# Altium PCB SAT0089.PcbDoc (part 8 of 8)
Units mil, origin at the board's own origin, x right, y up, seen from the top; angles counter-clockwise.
Board outline 4075 x 2715 mil, 6 copper layers (Top Layer, InternalPlane1, MidLayer1, Internal Plane 3, InternalPlane2, Bottom Layer), stack 67.4 mil thick; 538 components, 405 nets, 1716 pads, 1236 vias.
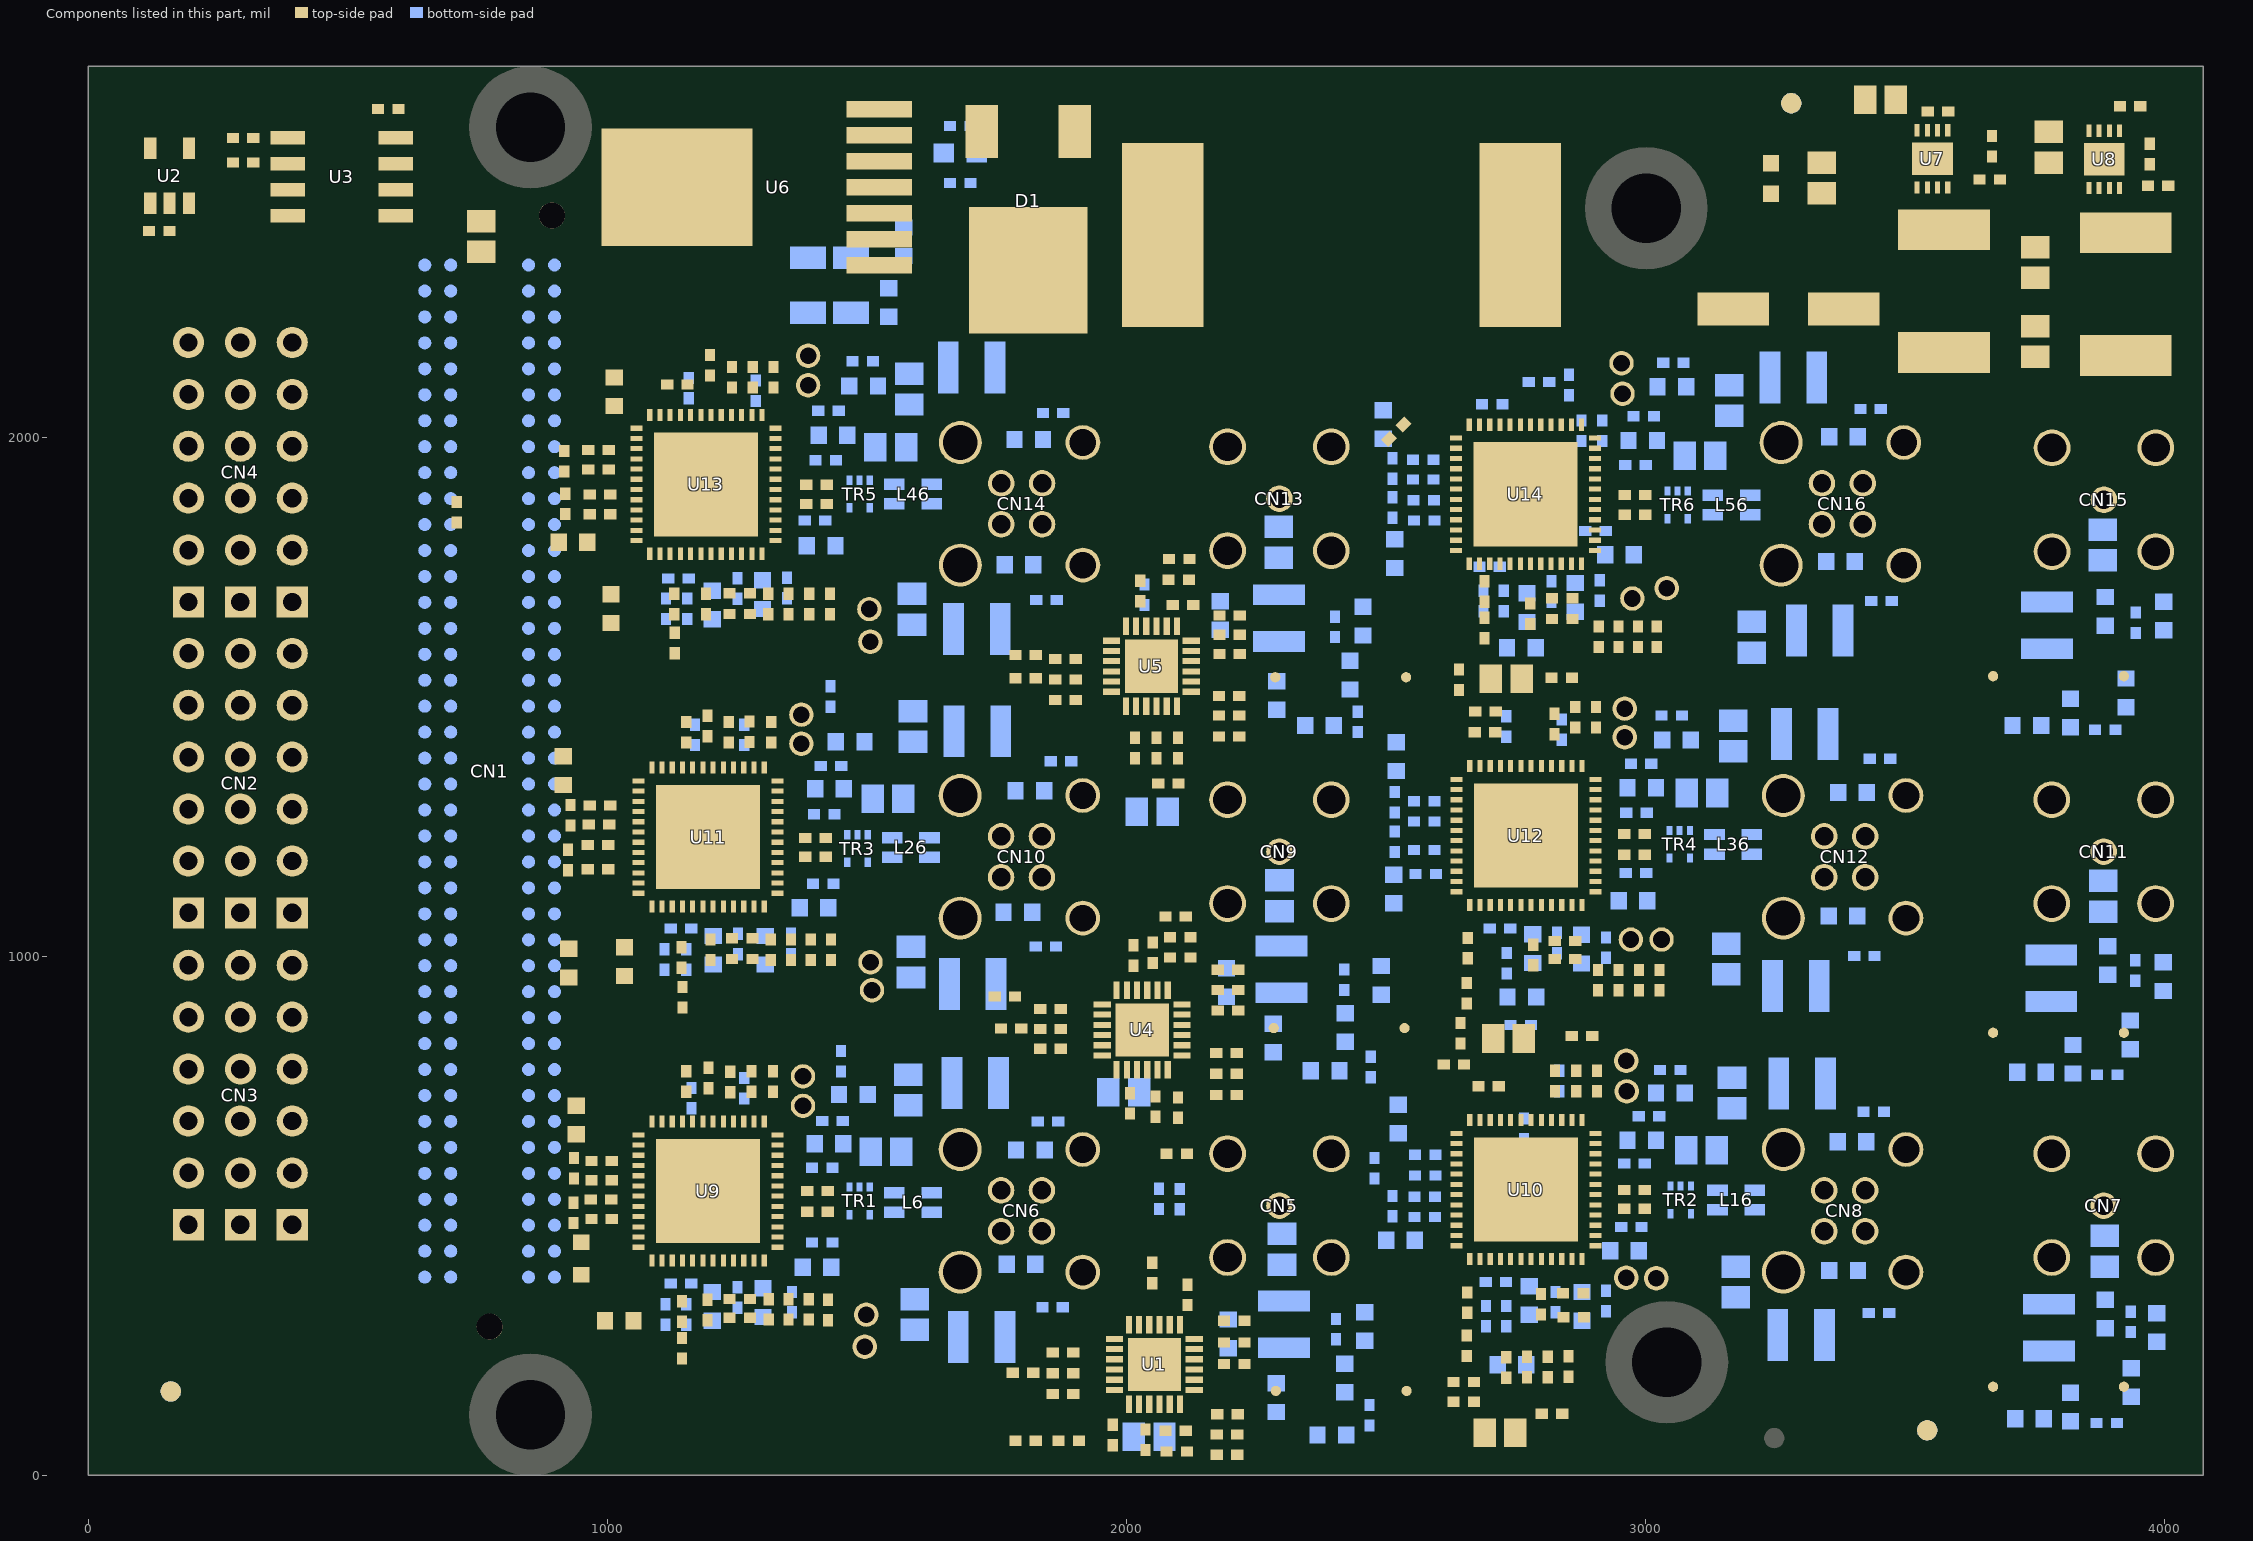
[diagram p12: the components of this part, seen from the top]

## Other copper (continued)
Internal Plane 3 (plane layer: these items are gaps in the copper):
  lines w12: 1015,855 1015,955 ; 1015,855 1060,810 ; 1015,855 1060,810 ; 1015,855 1015,955 ; 1015,955 1070,1010 ; 1015,955 1020,960 1070,1010 ; 1060,810 1060,600 900,600 900,890 900,1020 970,1020 970,1120 915,1120 915,1265 833,1265 833,2100 1005,2100 1010,2100 1010,1845 915,1845 915,1775 1010,1775 1010,1380 1065,1380 1070,1380 1070,1010 ; 1060,810 1060,570 1060,320 1025,320 1025,240 1160,240 1160,455 1160,680 1160,805 1090,875 1090,935 1165,935 1165,1140 1165,1510 1090,1510 1085,1510 1085,1675 1010,1675 1010,1385 1070,1385 1070,1010 ; 1390,1590 1400,1600 ; 1390,1590 1390,1310 1400,1295 1400,745 ; 1390,1590 1390,1305 1400,1290 1400,745 ; 1390,1590 1400,1600 ; 1390,1670 1230,1670 1230,1470 1230,1460 1305,1385 1305,240 1305,125 2045,125 2045,620 2020,620 2020,685 2440,685 2440,605 2515,605 2515,745 2080,745 2080,785 2190,785 2190,1045 2100,1135 2100,1340 2155,1395 2155,1575 1825,1575 1725,1575 1725,1545 1725,1485 1725,1475 1725,1445 1995,1445 2040,1400 2040,1395 2040,1345 2040,1135 2040,1015 2060,1015 2095,1015 2095,950 1820,950 1820,900 1710,900 1710,820 1710,760 1960,760 1960,270 1430,270 1430,715 ; 1390,1670 1400,1670 ; 1390,1670 1400,1670 ; 1390,1670 1390,2165 1495,2165 1495,1750 1535,1750 1565,1720 1565,1525 1480,1525 1480,1245 1480,1070 1570,1070 1590,1050 1590,745 1560,715 1490,715 1430,715 ; 1400,745 1430,715 ; 1400,745 1430,715 ; 1400,1600 1400,1670 ; 1400,1600 1400,1670 ; 2985,2160 3610,2160 ; 2985,2160 2985,820 2980,820 2840,820 2840,1175 2855,1175 2855,1235 2855,1375 2835,1375 2835,1665 2800,1665 2800,1975 2800,1991 2655,1991 2655,1940 2495,1940 2495,1965 2495,2030 2496,2041 2594,2041 2615,2062 2615,2170 2615,2265 3475,2265 3475,2315 3610,2315 3610,2160 ; 2985,2160 2985,750 2745,750 2745,1610 2665,1610 2665,900 2665,225 2675,225 2750,225 2750,235 2750,495 2820,565 2900,645 3115,645 3115,1330 3115,2020 3115,2035 3675,2035 3675,2190 3760,2190 3760,2135 3930,2135 3930,2155 3930,2190 3930,2305 3610,2305 3610,2160 ; 2985,2160 3610,2160
  lines w20: 4010,-1.1 58.7,-1.1 cw(c58.7,57.95) -0.35,57.95 -0.35,2656.38 cw(c58.7,2656.38) 58.7,2715.43 4015,2715.4 ; 4017.05,-1.1 ccw(c4017.05,57.95) 4076.1,57.95 ; 4017.05,2715.43 cw(c4017.05,2656.38) 4076.1,2656.38 ; 4076.1,47.95 4076.1,2646.38
  text ".Layer_Name" at 572,-861.49 h60

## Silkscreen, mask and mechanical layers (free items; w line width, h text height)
Top Overlay:
  circle w5.91: c503.32,60.58 r23.42
  region: 3026,880 3026,866 3052,873
  region: 2876,169 2894,136 2909,153
  region: 460,1705 460,1655 505,1655 505,1705
  region: 465,1110 465,1060 510,1060 510,1110
  region: 455,505 455,455 500,455 500,505
  lines w4: 2884,162 2941,105 2941,103 ; 2963,909 2999,873 3043,873
  text "C" at 497,51 h18.75
  text "2014" at 545,43 h31.25
  text ".Layer_Name" at 577,-858.49 h60
Bottom Overlay:
  rectangle: 1833,2174.5 2133,2274.5
  text ".PCB_Rev" at 2335,2184 h60
  text ".PRJ_Number" at 2799,2184.5 h60
  text "-" at 2198,2174 h60
  text ".Layer_Name" at 577,-858.49 h60
Top Paste:
  region: 2689.91,1812.04 2756.83,1812.04 2756.83,1878.97 2689.91,1878.97
  region: 2690.91,563.59 2757.83,563.59 2757.83,630.52 2690.91,630.52
  region: 2689.91,1902.59 2756.83,1902.59 2756.83,1969.52 2689.91,1969.52
  region: 2690.91,1245.59 2757.83,1245.59 2757.83,1312.52 2690.91,1312.52
  region: 2690.91,1155.04 2757.83,1155.04 2757.83,1221.97 2690.91,1221.97
  region: 2690.91,473.04 2757.83,473.04 2757.83,539.97 2690.91,539.97
  region: 1201.46,1921.59 1268.39,1921.59 1268.39,1988.52 1201.46,1988.52
  region: 1201.46,1831.04 1268.39,1831.04 1268.39,1897.97 1201.46,1897.97
  region: 1205.46,1241.59 1272.39,1241.59 1272.39,1308.52 1205.46,1308.52
  region: 1205.46,1151.04 1272.39,1151.04 1272.39,1217.97 1205.46,1217.97
  region: 1205.46,560.59 1272.39,560.59 1272.39,627.52 1205.46,627.52
  region: 1205.46,470.04 1272.39,470.04 1272.39,536.97 1205.46,536.97
  region: 2780.46,1812.04 2847.39,1812.04 2847.39,1878.97 2780.46,1878.97
  region: 2781.46,563.59 2848.39,563.59 2848.39,630.52 2781.46,630.52
  region: 2780.46,1902.59 2847.39,1902.59 2847.39,1969.52 2780.46,1969.52
  region: 2781.46,1245.59 2848.39,1245.59 2848.39,1312.52 2781.46,1312.52
  region: 2781.46,1155.04 2848.39,1155.04 2848.39,1221.97 2781.46,1221.97
  region: 2781.46,473.04 2848.39,473.04 2848.39,539.97 2781.46,539.97
  region: 1110.91,1921.59 1177.83,1921.59 1177.83,1988.52 1110.91,1988.52
  region: 1110.91,1831.04 1177.83,1831.04 1177.83,1897.97 1110.91,1897.97
  region: 1114.91,1241.59 1181.83,1241.59 1181.83,1308.52 1114.91,1308.52
  region: 1114.91,1151.04 1181.83,1151.04 1181.83,1217.97 1114.91,1217.97
  region: 1114.91,560.59 1181.83,560.59 1181.83,627.52 1114.91,627.52
  region: 1114.91,470.04 1181.83,470.04 1181.83,536.97 1114.91,536.97
  region: 3248.31,92.08 3240.63,90.55 3234.11,86.2 3229.76,79.69 3228.24,72.01 3229.76,64.33 3234.11,57.82 3240.63,53.46 3248.31,51.94 3255.99,53.46 3262.5,57.82 3266.85,64.33 3268.38,72.01 3266.85,79.69 3262.5,86.2 3255.99,90.55 3248.31,92.08
  text ".Layer_Name" at 577,-858.49 h60
Bottom Paste:
  text ".Layer_Name" at 577,-858.49 h60
Top Solder:
  region: 3248.31,131.35 3236.73,130.21 3225.6,126.83 3215.34,121.35 3206.35,113.97 3198.97,104.98 3193.48,94.72 3190.11,83.58 3188.97,72.01 3190.11,60.43 3193.48,49.3 3198.97,39.04 3206.35,30.05 3215.34,22.67 3225.6,17.18 3236.73,13.81 3248.31,12.67 3259.88,13.81 3271.02,17.18 3281.28,22.67 3290.27,30.05 3297.65,39.04 3303.13,49.3 3306.51,60.43 3307.65,72.01 3306.51,83.58 3303.13,94.72 3297.65,104.98 3290.27,113.97 3281.28,121.35 3271.02,126.83 3259.88,130.21 3248.31,131.35
  text ".Layer_Name" at 577,-858.49 h60
  text ".Layer_Name" at 577,-858.49 h60
Bottom Solder:
  text ".Layer_Name" at 577,-858.49 h60
Drill Guide:
  text ".Layer_Name" at 577,-858.49 h60
M1 Board Outline:
  the board outline again, w10
  text ".Layer_Name" at 577,-858.49 h60
M2 Board Dimensions:
  rectangle: -0.5,-285.5 124.5,-160.5
  rectangle: 124.5,-410.5 499.5,-285.5
  lines w7: -0.5,-285.5 999.5,-285.5 ; 124.5,-410.5 124.5,-160.5 ; 249.5,-410.5 249.5,-160.5 ; 499.5,-410.5 499.5,-160.5 ; 749.5,-410.5 749.5,-160.5 ; -0.5,-410.5 999.5,-410.5 999.5,-160.5 -0.5,-160.5 -0.5,-410.5
  lines w10: -0.5,-475.5 -0.5,-455.5 ; 59.5,-485.5 -0.5,-465.5 ; 59.5,-445.5 -0.5,-465.5 ; 223.58,-465.5 -0.5,-465.5 ; 775.42,-465.5 999.5,-465.5 ; 939.5,-485.5 999.5,-465.5 ; 939.5,-445.5 999.5,-465.5 ; 999.5,-475.5 999.5,-455.5
  text "1000 (mil)" at 233.58,-501.49 h60
  text ".Layer_Name" at 577,-858.49 h60
M3 3D STEP Top:
  text ".Layer_Name" at 577,-858.49 h60
M4 3D STEP Bottom:
  text ".Layer_Name" at 577,-858.49 h60
M5 Assembly Top:
  lines w10: -292,-930.17 6308,-930.17 ; -292,-726.83 6310,-726.83 ; -292,-523.5 -292,-1133.5 3713,-1133.5 6310,-1133.5 6310,-523.5 -291.5,-523.5 -291.5,-1133.5 1284,-1133.5 ; 2173,-1133.5 2173,-523.5 ; 3440,-726.83 3440,-523.5 ; 4280,-726.83 4280,-523.5 ; 4902,-1140 4902,-937.17
  text "COMPONENTS MARKED 'DNP' SHOULD NOT BE POPULATED." at 1153.5,-318.5 h60
  text "ASSEMBLY VARIANT:" at 1153,-434 h60
  text ".VariantName" at 2189,-434 h60
  text "PCB VIEWED FROM TOP SIDE" at -228.5,-655.67 h60
  text "BOARD #:" at 2248,-655.67 h60
  text ".PRJ_Number" at 2793.5,-655.67 h60
  text "REV:" at 3638,-655.67 h60
  text ".PCB_Rev" at 3929.5,-655.67 h60
  text "SVN REV:" at 4476,-655.67 h60
  text ".VersionControl_RevNumber" at 4982,-655.67 h60
  text "IGNORE ->" at -228.5,-858.49 h60
  text "PLOT NAME =" at -228.5,-1064.34 h60
  text ".plot_File_Name" at 577,-1064.34 h60
  text "GENERATED    :" at 2250,-1064.34 h60
  text ".Print_Date" at 3119.5,-1064.34 h60
  text ".Print_Time" at 3848.5,-1064.34 h60
  text "TEXAS INSTRUMENTS" at 5113,-1064.34 h60
M6 Assembly Bottom:
  lines w10: -292.5,-727.33 6309.5,-727.33 ; -290.5,-930.67 6309.5,-930.67 ; 1115.5,-1140.5 1115.5,-937.67 ; 1737.5,-727.33 1737.5,-524 ; 2577.5,-727.33 2577.5,-524 ; 3844.5,-1134 3844.5,-524 ; 4733.5,-1134 6309,-1134 6309,-524 -292.5,-524 -292.5,-1134 2304.5,-1134 6309.5,-1134 6309.5,-524
  text "COMPONENTS MARKED 'DNP' SHOULD NOT BE POPULATED." at 6102,-318 h60
  text ".VariantName" at 5058,-434 h60
  text "ASSEMBLY VARIANT:" at 6097,-434 h60
  text ".VersionControl_RevNumber" at 1035.5,-656.17 h60
  text "SVN REV:" at 1541.5,-656.17 h60
  text ".PCB_Rev" at 2088,-656.17 h60
  text "REV:" at 2379.5,-656.17 h60
  text ".PRJ_Number" at 3224,-656.17 h60
  text "BOARD #:" at 3769.5,-656.17 h60
  text "PCB VIEWED FROM BOTTOM SIDE" at 6246,-656.17 h60
  text "IGNORE ->" at 2547.85,-858.49 h60
  text "TEXAS INSTRUMENTS" at 904.5,-1064.84 h60
  text ".Print_Time" at 2169,-1064.84 h60
  text ".Print_Date" at 2898,-1064.84 h60
  text "GENERATED    :" at 3767.5,-1064.84 h60
  text ".plot_File_Name" at 5440.5,-1064.84 h60
  text "PLOT NAME =" at 6246,-1064.84 h60
M9 Title Sheet:
  drawing of 57 lines, arcs and shapes, not listed
  text "1" at 739.84,8036.5 h70
  text "2" at 3235.5,8036.5 h70
  text "3" at 5724.84,8036.5 h70
  text "4" at 8231.51,8036.5 h70
  text "5" at 10730.5,8036.5 h70
  text "6" at 13235.5,8036.5 h70
  text "A" at -416.5,6893.5 h70
  text "A" at 14383.5,6893.5 h70
  text "B" at -416.5,4513.5 h70
  text "B" at 14383.5,4513.5 h70
  text "C" at -416.5,2138.5 h70
  text "C" at 14383.5,2138.5 h70
  text "PROJECT TITLE:" at 11343.5,277.5 h45
  text ".PRJ_Title" at 11393.5,144.17 h70
  text "DESIGNED FOR:" at 11343.5,-23.5 h45
  text ".PRJ_Customer" at 11393.5,-163.5 h70
  text "D" at -416.5,-231.5 h70
  text "D" at 14383.5,-231.5 h70
  text "FILE NAME:" at 11343.5,-323.5 h45
  text ".PCB_File_Name_No_Path" at 11393.5,-443.5 h70
  text "Texas Instruments (TI) and/or its licensors do not warrant the accuracy or completeness of this specification" at 6374,-605.34 h45
  text "ENGINEER:" at 11343.5,-613.5 h45
  text "LAYOUT BY:" at 12848.5,-613.5 h45
  text "or any information contained therein. TI and/or its licensors do not warrant that this design will meet" at 6329.01,-718 h45
  text ".PRJ_Engineer" at 11393.5,-768.49 h70
  text ".PCB_Layout" at 12899,-768.49 h70
  text "the specifications, will be suitable for your application or fit for any particular purpose, or will operate in" at 6329.01,-830.67 h45
  text ".Layer_Name" at 577,-858.49 h60
  text "ALTIUM DESIGNER VERSION:" at 12848.5,-923.5 h45
  text "an implementation. TI and/or its licensors do not warrant that the design is production worthy. You should" at 6329.01,-943.33 h45
  text "completely validate and test your design implementation to confirm the system functionality for your application." at 6374,-1056 h45
  text ".print_Scale" at 11393.5,-1056.83 h70
  text ".Application_BuildNumber" at 12899,-1056.83 h70
  text "1" at 739.84,-1263.5 h70
  text "2" at 3235.5,-1263.5 h70
  text "3" at 5724.84,-1263.5 h70
  text "4" at 8231.51,-1263.5 h70
  text "5" at 10730.5,-1263.5 h70
  text "6" at 13235.5,-1263.5 h70
M10 Fab Notes:
  drawing of 212 lines, arcs and shapes, not listed
  text "DESIGN INFORMATION" at 12381.02,6810 h60
  text "(REFER ALSO ARRAY/PANEL PROFILING INFORMATION)" at 12019.46,6648.29 h60
  text "BOARD SIZE" at 11333.46,6644 h60
  text "2715MIL" at 11795.78,6516.18 h60
  text "X" at 12301.46,6516.18 h60
  text "4075MIL" at 12532.78,6516.18 h60
  text "Number of Layers :" at 11736.46,6319 h60
  text "6" at 12831.27,6309 h60
  text "MIN. TRACK WIDTH:" at 11736.46,6180 h60
  text "4" at 12832.7,6180 h60
  text "MIL" at 12987.46,6180 h60
  text "MIN. CLEARANCE:" at 11736.46,6048 h60
  text "5" at 12832.7,6048 h60
  text "MIL" at 12987.46,6048 h60
  text "MIN. VIA PAD SIZE:" at 11736.46,5916 h60
  text "19" at 12802.71,5916 h60
  text "MIL" at 12987.46,5916 h60
  text "0.05mm (2MIL)" at 12431.46,5774.29 h60
  text "MINIMUM ANNULAR RING" at 11407.23,5770 h60
  text "EXTERNAL" at 13139.46,5770 h60
  text "PER" at 11607.23,5652 h60
  text "IPC-D-275 CLASS 2 LEVEL C" at 11827.23,5652 h60
  text "MIL, HOLES" at 13315.46,5539.71 h60
  text "+/-" at 12923,5539 h60
  text "+/-" at 13777,5539 h60
  text "REGISTRATION TOLERANCES:" at 11407.23,5534 h60
  text "METAL" at 12607,5534 h60
  text "5" at 13183.2,5534 h60
  text "3" at 14016.2,5534 h60
  text "MIL" at 14132.46,5534 h60
  text "MATERIAL:" at 11332.46,5324.54 h60
  text "FR-4 High Tg" at 12318.9,5184.21 h60
  text "FR-408" at 11753.46,5175.64 h60
  text "X" at 12165.46,5175.64 h60
  text "OTHER" at 13241.46,5175.64 h60
  text "62 MIL (1.6mm) +/-10%" at 12073.56,5012.92 h60
  text "THICKNESS:" at 11407.23,5008.64 h60
  text "X" at 11945.4,5008.64 h60
  text "OTHER" at 13358.46,5008.64 h60
  text "TOLERANCE:" at 11407.23,4850.64 h60
  text "X" at 12246.53,4850.64 h60
  text "ANSI IPC-6012 TYPE 3 CLASS 2" at 12433.48,4850.64 h60
  text "OTHER +/-" at 12433.46,4694.64 h60
  text "BOW & TWIST:" at 11407.23,4537.64 h60
  text "X" at 12246.53,4537.64 h60
  text "ANSI IPC-6012 TYPE 3 CLASS 2" at 12433.48,4537.64 h60
  text "OTHER +/-" at 12433.46,4379.13 h60
  text "COPPER THICKNESS (FINISHED):" at 11332.46,4243.64 h60
  text "1.4MIL (1oz)" at 12212.46,4090.92 h60
  text "2MIL (1.4oz)" at 12979.46,4090.92 h60
  text "2.8MIL (2oz)" at 13706.46,4090.92 h60
  text "OUTER:" at 11689.46,4086.64 h60
  text "X" at 12084,4086 h60
  text "1.4MIL (1oz)" at 12212.46,3933.92 h60
  text "2.8MIL (2oz)" at 12979.46,3933.92 h60
  text "N/A" at 13706,3934.29 h60
  text "INNER SIGNAL:" at 11400.38,3929.64 h60
  text "X" at 12085.42,3929.64 h60
  text "DRILLING:" at 11332.46,3790.64 h60
  text "REFERENCE:" at 11407.23,3673.64 h60
  text "X" at 12055.46,3673.64 h60
  text "AS SHOWN" at 12242.46,3673.64 h60
  text "X" at 12956.46,3673.64 h60
  text "NC_DRILL FILES" at 13093.46,3673.64 h60
  text "PTH MIN COPPER THICKNESS:" at 11407.23,3515.64 h60
  text "X" at 12757.46,3515.64 h60
  text "1MIL" at 12894.46,3515.64 h60
  text "OTHER" at 13391.46,3515.64 h60
  text "BOARD FINISH:" at 11332.46,3356.64 h60
  text "SILKSCREEN:" at 11487.68,3238.64 h60
  text "X" at 12436.46,3238.64 h60
  text "TOP" at 12562.46,3238.64 h60
  text "X" at 12946.46,3238.64 h60
  text "BOTTOM" at 13073.46,3238.64 h60
  text "SILKSCREEN COLOR:" at 11487.68,3071.64 h60
  text "X" at 12435.42,3071.64 h60
  text "WHITE" at 12562.46,3071.64 h60
  text "OTHER" at 13073.46,3071.64 h60
  text "SOLDER RESIST COLOR:" at 11487.68,2901.64 h60
  text "RED" at 13787.46,2754.44 h60
  text "X" at 13164,2744 h60
  text "GREEN" at 12182.46,2742.44 h60
  text "BLUE" at 12773.46,2742.44 h60
  text "OTHER" at 13311.46,2742.44 h60
  text "IMMERSION GOLD (ENIG)" at 12393.46,2553.92 h60
  text "ENEPIG" at 13731,2550.64 h60
  text "SURFACE FINISH:" at 11332.46,2549.64 h60
  text "X" at 12206.51,2549.64 h60
  text "IMM. TIN/SILVER OR EQUIV" at 11662,2392.64 h60
  text "OTHER" at 13093.46,2392.64 h60
  text "ARRAY/PANEL:" at 11332.46,2213.64 h60
  text "CUT AND TRIM PER MECH LAYER 1" at 12393.46,2209.35 h60
  text "N.C. ROUTE" at 12393.46,2057.64 h60
  text "X" at 13072.46,2057.64 h60
  text "V. SCORE" at 13259.46,2057.64 h60
  text "CERTIFICATION:" at 11332.46,1920.64 h60
  text "MATERIALS AND WORKMANSHIP FOR ALL PCBS" at 12057.46,1920.64 h60
  text "TO MEET OR EXCEED THE REQUIREMENTS OF:" at 12057.46,1822.64 h60
  text "X" at 11683.96,1686.13 h60
  text "ANSI IPC-A-600F CLASS ->" at 11822.96,1686.13 h60
  text "X" at 13462.02,1686.13 h60
  text "2" at 13580.96,1686.14 h60
  text "1" at 13265.96,1684.64 h60
  text "3" at 13934.96,1684.64 h60
  text "X" at 11686.02,1526.64 h60
  text "UL 94V-0" at 11822.96,1526.64 h60
  text "X" at 12498.02,1526.64 h60
  text "RoHS" at 12634.96,1526.64 h60
  text "OTHER" at 13279.36,1526.64 h60
  text "PER ORDER" at 13676.42,1526.64 h60
  text "ADDITIONAL REQUIREMENTS:" at 11332.46,1385.64 h60
  text "MICROSECTION:" at 11407.23,1270.64 h60
  text "YES" at 12312.96,1270.64 h60
  text "REQUIRED" at 13174.46,1114.49 h60
  text "BARE BOARD ELEC. TEST:" at 11407.23,1111.64 h60
  text "NONE" at 12712.96,1111.64 h60
  text "X" at 13047.46,1111.64 h60
  text "PER ORDER" at 13766.46,1111.64 h60
  text "MANUFACTURER'S UL:" at 11407.23,954.64 h60
  text "RAIL" at 12572.96,950.35 h60
  text "METAL" at 13064.77,950.35 h60
  text "X" at 13440,950 h60
  text "SILK" at 13576.46,950.35 h60
  text ".Layer_Name" at 577,-858.49 h60
M11 Gerber Information:
  lines w10: -292,-930.17 6308,-930.17 ; -292,-726.83 6310,-726.83 ; -292,-523.5 -292,-1133.5 3713,-1133.5 6310,-1133.5 6310,-523.5 -291.5,-523.5 -291.5,-1133.5 1284,-1133.5 ; 2173,-1133.5 2173,-523.5 ; 3440,-726.83 3440,-523.5 ; 4280,-726.83 4280,-523.5 ; 4902,-1140 4902,-937.17
  text "ALL ARTWORK VIEWED FROM TOP SIDE" at -228.5,-655.67 h60
  text "BOARD #:" at 2248,-655.67 h60
  text ".PRJ_Number" at 2793.5,-655.67 h60
  text "REV:" at 3638,-655.67 h60
  text ".PCB_Rev" at 3929.5,-655.67 h60
  text "SVN REV:" at 4476,-655.67 h60
  text ".VersionControl_RevNumber" at 4982,-655.67 h60
  text "LAYER NAME =" at -228.5,-858.49 h60
  text "PLOT NAME =" at -228.5,-1064.34 h60
  text ".plot_File_Name" at 577,-1064.34 h60
  text "GENERATED    :" at 2250,-1064.34 h60
  text ".Print_Date" at 3119.5,-1064.34 h60
  text ".Print_Time" at 3848.5,-1064.34 h60
  text "TEXAS INSTRUMENTS" at 5113,-1064.34 h60
M12 Stackup:
  lines w5: 9568,7750.9 14236,7750.9 ; 9568,7846.1 14236,7846.1 ; 9508,6961 ccw(c9539,6961) 9539,6930 14265,6930 ccw(c14265,6961) 14296,6961 14296,7922 ccw(c14265,7922) 14265,7953 9539,7953 ccw(c9539,7922) 9508,7922 9508,6961
  text "Layer Stack Up Detail for: SAT0089.PcbDoc" at 9568,7869.25 h41
  text "Layer" at 9568,7810.6 h22
  text "Gerber" at 10479.83,7810.6 h22
  text "Copper" at 11091.82,7810.6 h22
  text "Dielectric" at 11739.74,7810.6 h22
  text "Dielectric" at 12403.05,7810.6 h22
  text "Dielectric" at 13159.93,7810.6 h22
  text "Dielectric" at 13823.24,7810.6 h22
  text "Name" at 9568,7766.6 h22
  text "Document" at 10479.83,7766.6 h22
  text "Thickness" at 11091.82,7766.6 h22
  text "Height" at 11739.74,7766.6 h22
  text "Material" at 12403.05,7766.6 h22
  text "Constant" at 13159.93,7766.6 h22
  text "Type" at 13823.24,7766.6 h22
  text "Top Solder Mask" at 9568,7703.64 h31
  text "(.GTS)" at 10479.83,7703.64 h31
  text "0.4mil" at 11739.74,7703.64 h31
  text "Solder Resist" at 12403.05,7703.64 h31
  text "3.50" at 13159.93,7703.64 h31
  text "Top Layer" at 9568,7614.13 h31
  text "(.GTL)" at 10479.83,7614.13 h31
  text "1.4mil" at 11091.82,7614.13 h31
  text "13mil" at 11739.74,7569.38 h31
  text "370HR" at 12403.05,7569.38 h31
  text "4.80" at 13159.93,7569.38 h31
  text "PrePreg" at 13823.24,7569.38 h31
  text "InternalPlane1" at 9568,7524.62 h31
  text "(.GP1)" at 10479.83,7524.62 h31
  text "1.4mil" at 11091.82,7524.62 h31
  text "10mil" at 11739.74,7479.86 h31
  text "370HR" at 12403.05,7479.86 h31
  text "4.80" at 13159.93,7479.86 h31
  text "Core" at 13823.24,7479.86 h31
  text "MidLayer1" at 9568,7435.11 h31
  text "(.G1)" at 10479.83,7435.11 h31
  text "1.4mil" at 11091.82,7435.11 h31
  text "13mil" at 11739.74,7390.35 h31
  text "370HR" at 12403.05,7390.35 h31
  text "4.80" at 13159.93,7390.35 h31
  text "PrePreg" at 13823.24,7390.35 h31
  text "Internal Plane 3" at 9568,7345.59 h31
  text "(.GP2)" at 10479.83,7345.59 h31
  text "1.4mil" at 11091.82,7345.59 h31
  text "10mil" at 11739.74,7300.84 h31
  text "370HR" at 12403.05,7300.84 h31
  text "4.80" at 13159.93,7300.84 h31
  text "Core" at 13823.24,7300.84 h31
  text "InternalPlane2" at 9568,7256.08 h31
  text "(.GP3)" at 10479.83,7256.08 h31
  text "1.4mil" at 11091.82,7256.08 h31
  text "13mil" at 11739.74,7211.33 h31
  text "370HR" at 12403.05,7211.33 h31
  text "4.80" at 13159.93,7211.33 h31
  text "PrePreg" at 13823.24,7211.33 h31
  text "Bottom Layer" at 9568,7166.57 h31
  text "(.GBL)" at 10479.83,7166.57 h31
  text "1.4mil" at 11091.82,7166.57 h31
  text "Bottom Solder Mask" at 9568,7077.06 h31
  text "(.GBS)" at 10479.83,7077.06 h31
  text "0.4mil" at 11739.74,7077.06 h31
  text "Solder Resist" at 12403.05,7077.06 h31
  text "3.50" at 13159.93,7077.06 h31
  text ".Layer_Name" at 577,-858.49 h60
M13 Component Bodies Top:
  text ".Layer_Name" at 577,-858.49 h60
M14 Component Bodies Bottom:
  text ".Layer_Name" at 577,-858.49 h60
M15 Courtyards Top:
  text ".Layer_Name" at 577,-858.49 h60
M16 Courtyards Bottom:
  text ".Layer_Name" at 577,-858.49 h60
Drill Drawing:
  text ".legend" at 4326.5,725.5 h60
  text "Drill Table" at 4351.5,540.5 h60
  text ".Layer_Name" at 577,-858.49 h60

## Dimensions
0,0 to 4075,0 on M2 Board Dimensions
0,0 to 0,2715 on M2 Board Dimensions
